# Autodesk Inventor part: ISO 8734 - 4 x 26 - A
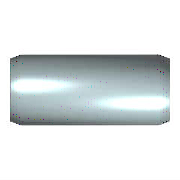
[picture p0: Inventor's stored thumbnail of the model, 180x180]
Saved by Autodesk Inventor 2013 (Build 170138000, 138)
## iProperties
IsCustomPart: 0
Created: 2012-02
Part Number: ISO 8734 - 4 x 26 - A
Material: Stahl
Description: Zylinderstift
Document SubType Name: Modeling
Standard: ISO 8734
Designer: rYan
Standards Organization: DIN
Language: de-DE
Size Designation: 4 x 26 - A
Categories: <MemberInstance><Categories><Category DisplayName="Verbindungselemente" InternalName="e4da775c-781d-43d5-af7c-5136215cf5a6" Mnemonic="FSTN"><Category DisplayNam
Density: 7.85 g/cm^3
Mass: 2.5546 g
Surface Area: 3.47662 cm^2
Volume: 0.325427 cm^3
Author: rYan
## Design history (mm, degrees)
sketch "Skizze"
  geometry: C1 r 2 at (0, 0); 1 further point
  constraints: 1 centre point, 1 coincident
  dimensions: "d1" = 4 diameter of C1 (= NND)
extrude "Körper" new body sketch "Skizze" distance "d2" = 26 (= NLG); taper "d3" = 0 deg
body "Solid1"
chamfer "Fase1" distance "d4" = 0.63 (= PHH); stored, may be unused: angle "d5" = 15 deg (= FAWI), second distance "d11" = 0.63 (= PHH)
chamfer "Fase2" distance "d8" = 0.63 (= PHH); stored, may be unused: angle "d9" = 15 deg (= FAWI), second distance "d12" = 0.63 (= PHH)
other parameters: "NND" = 4 [user parameter; used in 1 equation term], "NLG" = 26 [user parameter; used in 1 equation term], "PHH" = 0.63 [user parameter; used in 5 equation terms], "FAWI" = 15 deg [user parameter; used in 2 equation terms], "d13" = 0, "d15" = 0, "d16" = 0, "PHH2" = 0.63 (= PHH) [user parameter], "FAWI2" = 15 deg [user parameter]
